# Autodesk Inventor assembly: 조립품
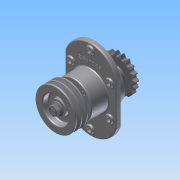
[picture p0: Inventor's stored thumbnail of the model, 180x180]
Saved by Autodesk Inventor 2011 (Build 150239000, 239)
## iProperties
Created: 2015-02
Part Number: 조립품
Document SubType Name: Assembly
Designer: SDA24
Author: SDA24
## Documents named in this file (12)
- C:\Users\SDA24\Desktop\450207V1023\조립품.iam
- C:\Users\SDA24\Desktop\450207V1023\본체.ipt
- C:\Users\SDA24\Desktop\450207V1023\450207V1023\2-커버.ipt
- C:\Users\SDA24\Desktop\450207V1023\450207V1023\6-베어링 6206.ipt
- C:\Users\SDA24\Desktop\450207V1023\450207V1023\7-부시.ipt
- C:\Users\SDA24\Desktop\450207V1023\450207V1023\3-축.ipt
- C:\Users\SDA24\Desktop\450207V1023\450207V1023\4-V벨트풀리.ipt
- C:\Users\SDA24\Desktop\450207V1023\450207V1023\5-체인 스프로킷.ipt
- C:\Users\SDA24\Desktop\450207V1023\450207V1023\8-오일실 30x42.ipt
- C:\Users\SDA24\Desktop\450207V1023\450207V1023\11-키 6x6.ipt
- C:\Users\SDA24\Desktop\450207V1023\450207V1023\9-M16-너트.ipt
- C:\Users\SDA24\Desktop\450207V1023\450207V1023\10-M6.ipt
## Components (22 placed, 10 different names)
1. 2-커버:1
2. 2-커버:2
3. 6-베어링 6206:1
4. 6-베어링 6206:2
5. 7-부시:1
6. 3-축:1
7. 4-V벨트풀리:1
8. 5-체인 스프로킷:1
9. 8-8-오일실 30x42:1
10. 8-8-오일실 30x42:2
11. 11-키 6x6:1
12. 11-키 6x6:2
13. 9-M16 너트:1
14. 9-M16 너트:2
15. 10-M6:1
16. 10-M6:2
17. 10-M6:3
18. 10-M6:4
19. 10-M6:5
20. 10-M6:6
21. 10-M6:7
22. 10-M6:8
